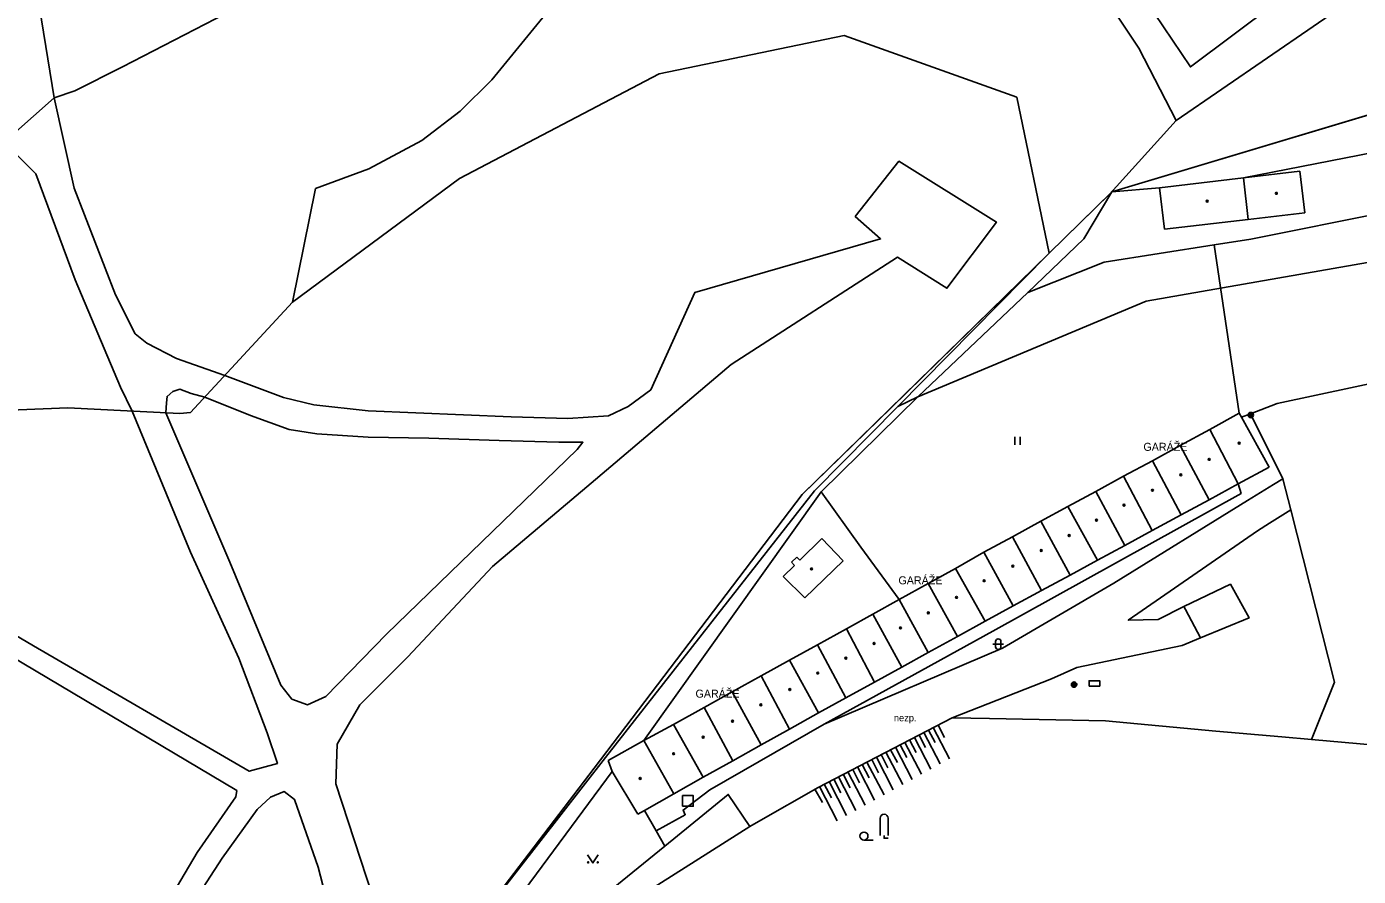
# Model space of a CAD drawing. Extents: x -598233 to -596890, y -1157848 to -1156431.
# Drawn here: x -597625.8 to -597501, y -1157280.2 to -1157200.6 of the extents above; entities that cross this region are included whole.
import ezdxf

# ---------------------------------------------------------------- set-up
doc = ezdxf.new("R2010")
doc.units = 0
for name, color, linetype in [('Level 1', 7, 'Continuous'), ('Level 11', 7, 'Continuous'), ('Level 15', 7, 'Continuous'), ('Level 24', 7, 'Continuous'), ('Level 25', 7, 'Continuous'), ('Level 26', 7, 'Continuous'), ('Level 36', 7, 'Continuous'), ('Level 39', 7, 'Continuous'), ('Level 40', 7, 'Continuous'), ('Level 41', 7, 'Continuous'), ('Level 5', 7, 'Continuous'), ('Level 51', 7, 'Continuous'), ('Level 52', 7, 'Continuous'), ('Vrstva 54', 7, 'Continuous'), ('Vrstva 60', 7, 'Continuous')]:
    doc.layers.add(name, color=color, linetype=linetype)

msp = doc.modelspace()

# ---------------------------------------------------------------- linework, layer by layer
at = {"layer": 'Level 1'}
msp.add_lwpolyline([(-597530.02, -1157221.88), (-597553.08, -1157244.43), (-597572.6, -1157270.07), (-597583.83, -1157284.82), (-597594.92, -1157321.55)], dxfattribs=at)
msp.add_lwpolyline([(-597530.02, -1157221.88), (-597553.08, -1157244.43), (-597572.6, -1157270.07), (-597583.83, -1157284.82), (-597594.92, -1157321.55)], dxfattribs=at)
at = {"layer": 'Level 11'}
for points in [[(-597643.5, -1157163.9), (-597643.17, -1157164.35), (-597643.9699, -1157165.9), (-597643.04, -1157168.13), (-597639.02, -1157171.21), (-597635.34, -1157174.61), (-597632.01, -1157178.44), (-597629.26, -1157182.68), (-597626.94, -1157187.82), (-597625.56, -1157192.6), (-597623.2, -1157207.27), (-597629.31, -1157212.68), (-597634.36, -1157216.59), (-597639.6, -1157219.12), (-597645.7, -1157221.25)], [(-597508.77, -1157198.42), (-597516.71, -1157204.37), (-597520.92, -1157198.1)], [(-597607.12, -1157199.37), (-597616.8, -1157204.37), (-597621.25, -1157206.59), (-597623.2, -1157207.27)], [(-597623.2, -1157207.27), (-597621.32, -1157215.72), (-597617.44, -1157225.72), (-597615.61, -1157229.37), (-597614.5, -1157230.25), (-597611.72, -1157231.68), (-597607.2, -1157233.27), (-597601.72, -1157235.33), (-597598.86, -1157236.04), (-597593.78, -1157236.6), (-597580.37, -1157237.15), (-597575.05, -1157237.31), (-597571.24, -1157237.07), (-597569.41, -1157236.2), (-597567.27, -1157234.61), (-597563.14, -1157225.49), (-597545.74, -1157220.48), (-597548.12, -1157218.37), (-597544.02, -1157213.21), (-597534.89, -1157218.9), (-597539.52, -1157225.11), (-597544.15, -1157222.2), (-597559.76, -1157232.26), (-597572.86, -1157243.37), (-597582.12, -1157251.18), (-597590.06, -1157259.64), (-597594.56, -1157264.14), (-597596.67, -1157267.84), (-597596.8, -1157271.55), (-597588.1, -1157298.06)], [(-597626.72, -1157212.58), (-597624.93, -1157214.38), (-597621.22, -1157224.33), (-597616.99, -1157234.38), (-597615.89, -1157236.61), (-597610.43, -1157249.83), (-597605.88, -1157259.78), (-597603.23, -1157266.77), (-597602.28, -1157269.63), (-597604.92, -1157270.37), (-597625.14, -1157258.62), (-597634.87, -1157252.9)], [(-597512.14, -1157236.81), (-597514.48, -1157221.05)], [(-597462.81, -1157226.14), (-597508.58, -1157235.9099), (-597511.09, -1157236.86)], [(-597574.18, -1157240.2), (-597592.04, -1157257.53), (-597597.73, -1157263.35), (-597599.45, -1157264.14), (-597600.91, -1157263.61), (-597601.96, -1157262.29), (-597606.73, -1157250.78), (-597612.73, -1157236.77), (-597612.68, -1157235.83), (-597612.61, -1157235.24), (-597612.08, -1157234.77), (-597611.42, -1157234.57), (-597610.36, -1157234.97), (-597609.09, -1157235.32), (-597604.81, -1157237.02), (-597601.17, -1157238.34), (-597598.59, -1157238.74), (-597593.76, -1157239.07), (-597588.07, -1157239.14), (-597581.49, -1157239.37), (-597575.9, -1157239.53), (-597573.65, -1157239.53), (-597574.18, -1157240.2)], [(-597511.09, -1157236.86), (-597511.93, -1157237.18)], [(-597511.09, -1157236.86), (-597508.04, -1157242.96)], [(-597551.03, -1157265.94), (-597534.32, -1157258.82), (-597523.89, -1157252.75), (-597511.37, -1157245), (-597508.92, -1157243.5), (-597508.04, -1157242.96)], [(-597512.2199, -1157243.44), (-597511.95, -1157244.33), (-597535.2199, -1157257.25), (-597551.03, -1157265.94)], [(-597508.04, -1157242.96), (-597507.3, -1157245.86)], [(-597551.31, -1157244.18), (-597547.6, -1157249.38), (-597544, -1157254.28)], [(-597519.74, -1157256.1599), (-597522.53, -1157256.2199), (-597510.42, -1157247.85), (-597509.29, -1157247.13), (-597507.3, -1157245.86)], [(-597507.3, -1157245.86), (-597503.19, -1157262.02)], [(-597640.42, -1157251.76), (-597606.09, -1157272.17)], [(-597517.32, -1157254.92), (-597512.95, -1157252.84), (-597511.2, -1157255.99), (-597515.76, -1157257.87)], [(-597517.32, -1157254.92), (-597519.74, -1157256.1599)], [(-597517.32, -1157254.92), (-597517.17, -1157255.2), (-597515.76, -1157257.87)], [(-597539.03, -1157265.36), (-597529.73, -1157261.71), (-597527.34, -1157260.63), (-597517.49, -1157258.59)], [(-597517.49, -1157258.59), (-597515.76, -1157257.87)], [(-597451.89, -1157258.39), (-597469.86, -1157270.53), (-597505.36, -1157267.39)], [(-597503.19, -1157262.02), (-597505.36, -1157267.39)], [(-597551.03, -1157265.94), (-597561.74, -1157272.11), (-597564.26, -1157274), (-597564.05, -1157274.44), (-597566.77, -1157275.96)], [(-597539.03, -1157265.36), (-597551.61, -1157271.88), (-597557.19, -1157275.08)], [(-597514.31, -1157266.61), (-597524.67, -1157265.65), (-597535.5368, -1157265.4307), (-597539.03, -1157265.36)], [(-597505.36, -1157267.39), (-597508.124, -1157267.1491), (-597514.31, -1157266.61)], [(-597628.21, -1157295.24), (-597615.61, -1157301.06), (-597614.45, -1157298.31), (-597620.8, -1157295.24), (-597621.12, -1157294.18), (-597619, -1157292.38), (-597616.6, -1157290.3), (-597613.14, -1157286.57), (-597610.32, -1157282.96), (-597607.46, -1157278.52), (-597604.18, -1157273.96), (-597602.91, -1157272.8), (-597601.64, -1157272.27), (-597600.69, -1157273.01), (-597598.47, -1157279.36), (-597596.88, -1157285.39), (-597596.08, -1157294.4), (-597594.97, -1157300.74), (-597588.1, -1157298.06)], [(-597606.09, -1157272.17), (-597606.17, -1157272.77), (-597609.79, -1157277.99), (-597612.86, -1157283.17), (-597614.97, -1157285.71), (-597619.74, -1157289.95), (-597621.96, -1157291.74), (-597623.44, -1157292.27), (-597625.77, -1157290.26), (-597627.57, -1157289.2)], [(-597558, -1157275.54), (-597560.02, -1157272.54), (-597565.9699, -1157277.38)], [(-597566.77, -1157275.96), (-597567.86, -1157274.03)], [(-597557.19, -1157275.08), (-597558, -1157275.54)], [(-597558, -1157275.54), (-597570.12, -1157283.23), (-597572.39, -1157285.84)], [(-597566.77, -1157275.96), (-597565.9699, -1157277.38)], [(-597565.9699, -1157277.38), (-597574.31, -1157284.17)]]:
    msp.add_lwpolyline(points, dxfattribs=at)
at = {"layer": 'Level 15'}
for points in [[(-597541.25, -1157266.51), (-597540.64, -1157267.68)], [(-597540.81, -1157266.28), (-597539.29, -1157269.2)], [(-597540.36, -1157266.05), (-597539.76, -1157267.21)], [(-597543.4699, -1157267.6599), (-597541.92, -1157270.65)], [(-597543.02, -1157267.43), (-597542.4099, -1157268.62)], [(-597542.58, -1157267.2), (-597541.05, -1157270.1599)], [(-597542.14, -1157266.9699), (-597541.53, -1157268.15)], [(-597541.69, -1157266.74), (-597540.17, -1157269.68)], [(-597546.13, -1157269.04), (-597544.55, -1157272.1)], [(-597545.69, -1157268.81), (-597545.06, -1157270.03)], [(-597545.24, -1157268.58), (-597543.67, -1157271.61)], [(-597544.8, -1157268.35), (-597544.17, -1157269.56)], [(-597544.36, -1157268.12), (-597542.8, -1157271.13)], [(-597543.9099, -1157267.89), (-597543.29, -1157269.09)], [(-597548.35, -1157270.19), (-597547.71, -1157271.44)], [(-597547.9099, -1157269.96), (-597546.3, -1157273.06)], [(-597547.46, -1157269.73), (-597546.82, -1157270.9699)], [(-597547.02, -1157269.5), (-597545.42, -1157272.58)], [(-597546.58, -1157269.27), (-597545.94, -1157270.5)], [(-597551.02, -1157271.57), (-597550.35, -1157272.85)], [(-597550.57, -1157271.34), (-597548.93, -1157274.52)], [(-597550.13, -1157271.11), (-597549.4699, -1157272.38)], [(-597549.68, -1157270.88), (-597548.05, -1157274.03)], [(-597549.24, -1157270.65), (-597548.59, -1157271.9099)], [(-597548.8, -1157270.42), (-597547.18, -1157273.55)], [(-597551.9, -1157272.04), (-597551.18, -1157273.29)], [(-597551.46, -1157271.8), (-597549.8, -1157275)]]:
    msp.add_lwpolyline(points, dxfattribs=at)
at = {"layer": 'Level 24'}
msp.add_lwpolyline([(-597526.21, -1157262.39), (-597525.21, -1157262.39), (-597525.21, -1157261.89), (-597526.21, -1157261.89)], close=True, dxfattribs=at)
at = {"layer": 'Level 25'}
for centre, radius in [((-597511.04, -1157236.99), 0.25), ((-597511.04, -1157236.99), 0.2), ((-597511.04, -1157236.99), 0.15), ((-597511.04, -1157236.99), 0.1), ((-597511.04, -1157236.99), 0.05), ((-597527.61, -1157262.25), 0.25), ((-597527.61, -1157262.25), 0.2), ((-597527.61, -1157262.25), 0.15), ((-597527.61, -1157262.25), 0.1), ((-597527.61, -1157262.25), 0.05)]:
    msp.add_circle(centre, radius, dxfattribs=at)
at = {"layer": 'Level 26'}
msp.add_lwpolyline([(-597564.3, -1157273.65), (-597563.3, -1157273.65), (-597563.3, -1157272.65), (-597564.3, -1157272.65)], close=True, dxfattribs=at)
at = {"layer": 'Level 36'}
for p, q in [((-597533.164, -1157239.763), (-597533.164, -1157239.013)), ((-597532.664, -1157239.763), (-597532.664, -1157239.013)), ((-597535.216, -1157258.456), (-597534.216, -1157258.456)), ((-597534.966, -1157258.206), (-597534.966, -1157258.706)), ((-597534.466, -1157258.206), (-597534.466, -1157258.706)), ((-597545.7849, -1157274.775), (-597545.7849, -1157276.4)), ((-597545.0349, -1157274.775), (-597545.0349, -1157276.4)), ((-597547.3, -1157276.815), (-597546.425, -1157276.815))]:
    msp.add_line(p, q, dxfattribs=at)
for points in [[(-597545.4099, -1157276.4), (-597545.4099, -1157276.65), (-597545.0349, -1157276.65)], [(-597573.2, -1157278.2), (-597572.7, -1157278.95), (-597572.2, -1157278.2)]]:
    msp.add_lwpolyline(points, dxfattribs=at)
for centre, radius in [((-597547.3001, -1157276.4399), 0.375), ((-597573.1502, -1157278.8998), 0.05), ((-597572.2508, -1157278.8998), 0.05)]:
    msp.add_circle(centre, radius, dxfattribs=at)
for centre, radius, start, end in [((-597534.7157, -1157258.2063), 0.25, 0, 180), ((-597534.7157, -1157258.7063), 0.25, 180, 0), ((-597545.4102, -1157274.7746), 0.375, 0, 180)]:
    msp.add_arc(centre, radius, start, end, dxfattribs=at)
at = {"layer": 'Level 39'}
for centre, radius in [((-597508.65, -1157216.21), 0.09), ((-597508.65, -1157216.21), 0.0398), ((-597515.13, -1157216.94), 0.09), ((-597515.13, -1157216.94), 0.0398), ((-597512.13, -1157239.61), 0.09), ((-597512.13, -1157239.61), 0.0398), ((-597514.94, -1157241.14), 0.09), ((-597514.94, -1157241.14), 0.0398), ((-597517.61, -1157242.6), 0.09), ((-597517.61, -1157242.6), 0.0398), ((-597520.27, -1157244.04), 0.09), ((-597520.27, -1157244.04), 0.0398), ((-597522.93, -1157245.42), 0.09), ((-597522.93, -1157245.42), 0.0398), ((-597525.51, -1157246.84), 0.09), ((-597525.51, -1157246.84), 0.0398), ((-597528.07, -1157248.28), 0.09), ((-597528.07, -1157248.28), 0.0398), ((-597530.68, -1157249.68), 0.09), ((-597530.68, -1157249.68), 0.0398), ((-597552.21, -1157251.4099), 0.09), ((-597552.21, -1157251.4099), 0.0398), ((-597533.36, -1157251.14), 0.09), ((-597533.36, -1157251.14), 0.0398), ((-597536.04, -1157252.51), 0.09), ((-597536.04, -1157252.51), 0.0398), ((-597538.62, -1157254.07), 0.09), ((-597538.62, -1157254.07), 0.0398), ((-597541.27, -1157255.53), 0.09), ((-597541.27, -1157255.53), 0.0398), ((-597543.88, -1157256.94), 0.09), ((-597543.88, -1157256.94), 0.0398), ((-597546.36, -1157258.39), 0.09), ((-597546.36, -1157258.39), 0.0398), ((-597549, -1157259.76), 0.09), ((-597549, -1157259.76), 0.0398), ((-597551.64, -1157261.1599), 0.09), ((-597551.64, -1157261.1599), 0.0398), ((-597554.26, -1157262.71), 0.09), ((-597554.26, -1157262.71), 0.0398), ((-597556.96, -1157264.15), 0.09), ((-597556.96, -1157264.15), 0.0398), ((-597559.62, -1157265.68), 0.09), ((-597559.62, -1157265.68), 0.0398), ((-597562.37, -1157267.18), 0.09), ((-597562.37, -1157267.18), 0.0398), ((-597565.14, -1157268.7199), 0.09), ((-597565.14, -1157268.7199), 0.0398), ((-597568.27, -1157271.04), 0.09), ((-597568.27, -1157271.04), 0.0398)]:
    msp.add_circle(centre, radius, dxfattribs=at)
at = {"layer": 'Level 5'}
for points in [[(-597512.14, -1157236.81), (-597514.89, -1157238.33)], [(-597512.14, -1157236.81), (-597511.93, -1157237.18)], [(-597511.93, -1157237.18), (-597509.34, -1157241.88)], [(-597514.89, -1157238.33), (-597517.67, -1157239.85)], [(-597514.89, -1157238.33), (-597512.2199, -1157243.44)], [(-597517.67, -1157239.85), (-597520.26, -1157241.28)], [(-597517.67, -1157239.85), (-597514.95, -1157244.92)], [(-597520.26, -1157241.28), (-597522.98, -1157242.7199)], [(-597520.26, -1157241.28), (-597517.56, -1157246.34)], [(-597522.98, -1157242.7199), (-597525.57, -1157244.14)], [(-597522.98, -1157242.7199), (-597520.3, -1157247.82)], [(-597509.34, -1157241.88), (-597512.2199, -1157243.44)], [(-597512.2199, -1157243.44), (-597514.95, -1157244.92)], [(-597525.57, -1157244.14), (-597528.18, -1157245.57)], [(-597525.57, -1157244.14), (-597522.84, -1157249.2)], [(-597514.95, -1157244.92), (-597517.56, -1157246.34)], [(-597528.18, -1157245.57), (-597530.7199, -1157246.94)], [(-597528.18, -1157245.57), (-597525.42, -1157250.6)], [(-597517.56, -1157246.34), (-597520.3, -1157247.82)], [(-597530.7199, -1157246.94), (-597533.39, -1157248.4099)], [(-597530.7199, -1157246.94), (-597527.9699, -1157251.98)], [(-597520.3, -1157247.82), (-597522.84, -1157249.2)], [(-597551.24, -1157248.57), (-597553.3, -1157250.58)], [(-597551.24, -1157248.57), (-597549.25, -1157250.64)], [(-597533.39, -1157248.4099), (-597536.08, -1157249.84)], [(-597533.39, -1157248.4099), (-597530.65, -1157253.43)], [(-597553.59, -1157250.29), (-597554.09, -1157250.78)], [(-597553.59, -1157250.29), (-597553.3, -1157250.58)], [(-597536.08, -1157249.84), (-597538.73, -1157251.37)], [(-597536.08, -1157249.84), (-597533.32, -1157254.88)], [(-597522.84, -1157249.2), (-597525.42, -1157250.6)], [(-597553.8, -1157251.07), (-597554.88, -1157252.13)], [(-597554.09, -1157250.78), (-597553.8, -1157251.07)], [(-597549.25, -1157250.64), (-597552.85, -1157254.11)], [(-597538.73, -1157251.37), (-597541.3, -1157252.78)], [(-597538.73, -1157251.37), (-597535.93, -1157256.3)], [(-597525.42, -1157250.6), (-597527.9699, -1157251.98)], [(-597554.88, -1157252.13), (-597552.85, -1157254.11)], [(-597541.3, -1157252.78), (-597544, -1157254.28)], [(-597541.3, -1157252.78), (-597538.53, -1157257.73)], [(-597527.9699, -1157251.98), (-597530.65, -1157253.43)], [(-597530.65, -1157253.43), (-597533.32, -1157254.88)], [(-597544, -1157254.28), (-597546.4699, -1157255.64)], [(-597544, -1157254.28), (-597541.29, -1157259.25)], [(-597533.32, -1157254.88), (-597535.93, -1157256.3)], [(-597546.4699, -1157255.64), (-597548.95, -1157257.01)], [(-597546.4699, -1157255.64), (-597543.76, -1157260.61)], [(-597535.93, -1157256.3), (-597538.53, -1157257.73)], [(-597548.95, -1157257.01), (-597551.67, -1157258.51)], [(-597548.95, -1157257.01), (-597546.33, -1157262.02)], [(-597538.53, -1157257.73), (-597541.29, -1157259.25)], [(-597551.67, -1157258.51), (-597554.29, -1157259.96)], [(-597551.67, -1157258.51), (-597549, -1157263.49)], [(-597554.29, -1157259.96), (-597556.95, -1157261.43)], [(-597554.29, -1157259.96), (-597551.56, -1157264.9)], [(-597541.29, -1157259.25), (-597543.76, -1157260.61)], [(-597556.95, -1157261.43), (-597559.6599, -1157262.93)], [(-597556.95, -1157261.43), (-597554.28, -1157266.4099)], [(-597543.76, -1157260.61), (-597546.33, -1157262.02)], [(-597546.33, -1157262.02), (-597549, -1157263.49)], [(-597559.6599, -1157262.93), (-597562.29, -1157264.39)], [(-597559.6599, -1157262.93), (-597556.94, -1157267.9)], [(-597549, -1157263.49), (-597551.56, -1157264.9)], [(-597562.29, -1157264.39), (-597565.1599, -1157265.9699)], [(-597562.29, -1157264.39), (-597559.6, -1157269.38)], [(-597551.56, -1157264.9), (-597554.28, -1157266.4099)], [(-597565.1599, -1157265.9699), (-597567.92, -1157267.49)], [(-597565.1599, -1157265.9699), (-597562.38, -1157270.93)], [(-597554.28, -1157266.4099), (-597556.94, -1157267.9)], [(-597567.92, -1157267.49), (-597571.27, -1157269.35)], [(-597567.92, -1157267.49), (-597565.12, -1157272.48)], [(-597556.94, -1157267.9), (-597559.6, -1157269.38)], [(-597571.27, -1157269.35), (-597570.89, -1157270.38)], [(-597559.6, -1157269.38), (-597562.38, -1157270.93)], [(-597570.89, -1157270.38), (-597568.49, -1157274.38)], [(-597562.38, -1157270.93), (-597565.12, -1157272.48)], [(-597565.12, -1157272.48), (-597567.86, -1157274.03)], [(-597567.86, -1157274.03), (-597568.49, -1157274.38)]]:
    msp.add_lwpolyline(points, dxfattribs=at)
at = {"layer": 'Level 51'}
for points in [[(-597496.65, -1157194.67), (-597518.05, -1157209.37)], [(-597582.18, -1157205.59), (-597577.12, -1157199.4)], [(-597523.6, -1157199.52), (-597521.53, -1157202.62)], [(-597566.51, -1157205.02), (-597549.17, -1157201.4099)], [(-597549.17, -1157201.4099), (-597532.9699, -1157207.21)], [(-597521.53, -1157202.62), (-597518.05, -1157209.37)], [(-597585.2199, -1157214.83), (-597566.51, -1157205.02)], [(-597585.14, -1157208.52), (-597582.18, -1157205.59)], [(-597532.9699, -1157207.21), (-597529.96, -1157221.82)], [(-597496.65, -1157207.84), (-597524.08, -1157216.07)], [(-597496.65, -1157207.84), (-597524.08, -1157216.07)], [(-597588.74, -1157211.26), (-597585.14, -1157208.52)], [(-597518.05, -1157209.37), (-597524.23, -1157216.2199)], [(-597518.05, -1157209.37), (-597524.23, -1157216.2199)], [(-597593.7, -1157213.9), (-597588.74, -1157211.26)], [(-597495.43, -1157211.56), (-597511.73, -1157214.75)], [(-597598.7199, -1157215.75), (-597593.7, -1157213.9)], [(-597600.85, -1157226.42), (-597585.2199, -1157214.83)], [(-597600.85, -1157226.42), (-597598.7199, -1157215.75)], [(-597524.23, -1157216.2199), (-597529.96, -1157221.82)], [(-597524.23, -1157216.2199), (-597529.96, -1157221.82)], [(-597524.08, -1157216.07), (-597526.7, -1157220.46)], [(-597524.08, -1157216.07), (-597526.7, -1157220.46)], [(-597519.61, -1157215.68), (-597524.08, -1157216.07)], [(-597519.61, -1157215.68), (-597524.08, -1157216.07)], [(-597511.05, -1157220.51), (-597498.26, -1157217.93)], [(-597526.7, -1157220.46), (-597531.93, -1157225.49)], [(-597524.78, -1157222.66), (-597514.48, -1157221.05), (-597511.05, -1157220.51)], [(-597529.96, -1157221.82), (-597530.02, -1157221.88), (-597544.12, -1157236.18)], [(-597529.96, -1157221.82), (-597530.02, -1157221.88), (-597544.12, -1157236.18)], [(-597531.93, -1157225.49), (-597524.78, -1157222.6599)], [(-597520.84, -1157226.3), (-597494.21, -1157221.67)], [(-597610.4099, -1157236.74), (-597600.85, -1157226.42)], [(-597531.93, -1157225.49), (-597542.26, -1157235.28)], [(-597542.26, -1157235.28), (-597520.84, -1157226.3)], [(-597542.26, -1157235.28), (-597551.31, -1157244.18)], [(-597542.26, -1157235.28), (-597544.12, -1157236.18)], [(-597630.42, -1157236.64), (-597621.93, -1157236.32)], [(-597621.93, -1157236.32), (-597611.42, -1157236.83)], [(-597544.12, -1157236.18), (-597551.93, -1157244.09)], [(-597611.42, -1157236.83), (-597610.4099, -1157236.74)], [(-597551.93, -1157244.09), (-597571.52, -1157269.08)], [(-597551.31, -1157244.18), (-597567.92, -1157267.49)], [(-597571.52, -1157269.08), (-597584.08, -1157285.18)], [(-597571.52, -1157269.08), (-597584.08, -1157285.18)], [(-597582.9699, -1157286.69), (-597570.89, -1157270.38)]]:
    msp.add_lwpolyline(points, dxfattribs=at)
at = {"layer": 'Level 52'}
for points in [[(-597511.73, -1157214.75), (-597506.45, -1157214.13)], [(-597506.45, -1157214.13), (-597505.99, -1157218.04)], [(-597519.61, -1157215.68), (-597511.73, -1157214.75)], [(-597511.28, -1157218.6599), (-597511.73, -1157214.75)], [(-597519.15, -1157219.58), (-597519.61, -1157215.68)], [(-597511.28, -1157218.6599), (-597519.15, -1157219.58)], [(-597505.99, -1157218.04), (-597511.28, -1157218.6599)]]:
    msp.add_lwpolyline(points, dxfattribs=at)
at = {"layer": 'Vrstva 54'}
for p, q in [((-597496.65, -1157207.84), (-597524.08, -1157216.07)), ((-597524.08, -1157216.07), (-597544.75, -1157236.3)), ((-597544.75, -1157236.3), (-597553.08, -1157244.43)), ((-597553.08, -1157244.43), (-597572.6, -1157270.07)), ((-597572.6, -1157270.07), (-597583.83, -1157284.82))]:
    msp.add_line(p, q, dxfattribs=at)
at = {"layer": 'Vrstva 60'}
for points in [[(-597429.64, -1157145.11), (-597450.24, -1157168.12), (-597452.46, -1157170.6), (-597474.26, -1157198.23), (-597496.65, -1157207.84), (-597524.08, -1157216.07), (-597544.75, -1157236.3), (-597553.08, -1157244.43), (-597572.6, -1157270.07), (-597583.83, -1157284.82), (-597594.92, -1157321.55), (-597604.05, -1157339.11), (-597605.14, -1157343.41), (-597602.86, -1157350.98), (-597590.7, -1157366.5), (-597575.19, -1157387.68)], [(-597575.19, -1157387.68), (-597590.7, -1157366.5), (-597602.86, -1157350.98), (-597605.14, -1157343.41), (-597604.05, -1157339.11), (-597594.92, -1157321.55), (-597583.83, -1157284.82), (-597572.6, -1157270.07), (-597553.08, -1157244.43), (-597544.75, -1157236.3), (-597524.08, -1157216.07), (-597496.65, -1157207.84), (-597474.26, -1157198.23), (-597452.46, -1157170.6), (-597450.24, -1157168.12), (-597429.64, -1157145.11)]]:
    msp.add_lwpolyline(points, dxfattribs=at)

# ---------------------------------------------------------------- texts
at = {"layer": 'Level 40'}
msp.add_text('nezp.', height=0.65, dxfattribs=at).set_placement((-597544.5, -1157265.69))
at = {"layer": 'Level 41'}
for p in [(-597521.11, -1157240.34), (-597544.07, -1157252.85), (-597563.09, -1157263.4699)]:
    msp.add_text('GARÁŽE', height=0.75, dxfattribs=at).set_placement(p)

doc.saveas('drawing.dxf')
